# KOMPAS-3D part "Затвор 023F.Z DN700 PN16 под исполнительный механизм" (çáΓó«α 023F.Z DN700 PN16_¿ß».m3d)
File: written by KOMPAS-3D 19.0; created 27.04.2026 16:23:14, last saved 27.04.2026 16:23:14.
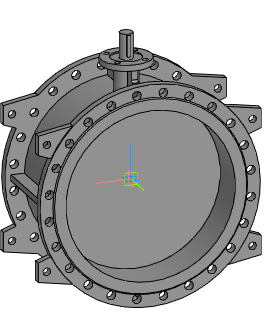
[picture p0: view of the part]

Document properties: Автор: Евгений; Полное имя файла: Z:\3.Личные\kachalov\3d для проектировщиков\1.7 Тип 023F.Z Затвор дисковый поворотный фланцевый с двумя эксцентриками\Затвор 023F.Z DN200-DN1600_исп\_stp_Затвор 023F.Z DN200-DN1600_исп\Затвор 023F.Z DN700 PN16_исп.m3d

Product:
- Part/product: Затвор 023F.Z DN700 PN16 под исполнительный механизм

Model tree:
1. Операция без истории:1  (labels: Затвор 023F.Z DN700 PN16 под исполнительный механизм)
